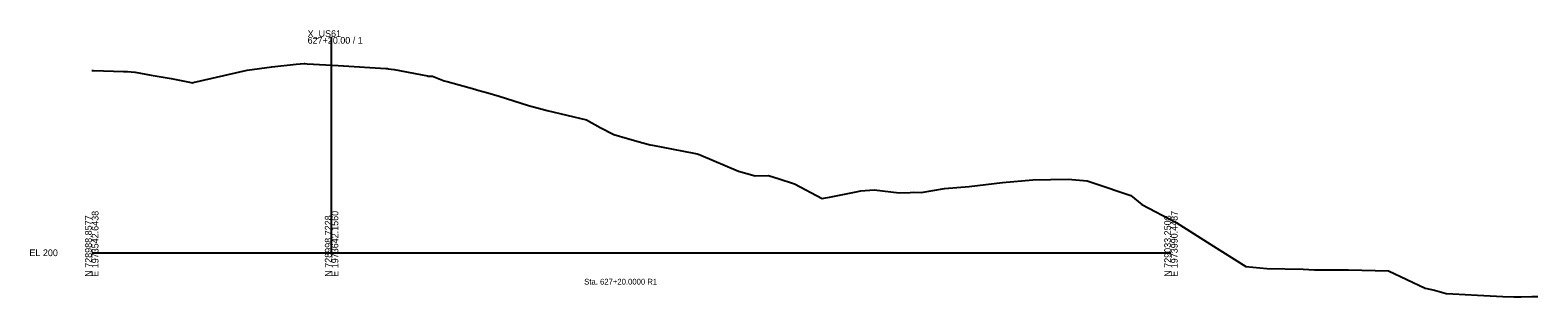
# Model space of a CAD drawing. Extents: x -26 to 630, y -39 to 9098.
# Drawn here: x -26 to 603, y 7982 to 8093 of the extents above; entities that cross this region are included whole.
import ezdxf

# ---------------------------------------------------------------- set-up
doc = ezdxf.new("R2010")
doc.units = 0
for name, color, linetype in [('Draft_XS_Grid', 7, 'Continuous'), ('Draft_XS_Text', 7, 'Continuous'), ('DTM_X_GROUND', 7, 'Continuous'), ('XS_CELL', 7, 'Continuous')]:
    doc.layers.add(name, color=color, linetype=linetype)

msp = doc.modelspace()

# ---------------------------------------------------------------- linework, layer by layer
at = {"layer": 'DTM_X_GROUND'}
msp.add_lwpolyline([(0, 8076.05), (0.74, 8076.06), (13.22, 8075.66), (14.93, 8075.6), (17.96, 8075.3), (18.04, 8075.3), (24.75, 8074.11), (33.1, 8072.62), (40.81, 8071.09), (41.84, 8070.89), (42.24, 8070.99), (64.86, 8076.14), (75.07, 8077.6), (85.2, 8078.68), (88.58, 8078.9), (88.78, 8078.91), (89.83, 8078.86), (102.75, 8078.16), (122.67, 8076.85), (123.48, 8076.79), (123.61, 8076.77), (126.15, 8076.41), (137.04, 8074.33), (139.99, 8073.75), (140.27, 8073.67), (141.64, 8073.7), (142.13, 8073.63), (146.24, 8071.98), (147, 8071.77), (148.15, 8071.44), (159.7, 8068.23), (161.01, 8067.77), (165.12, 8066.69), (169.91, 8065.31), (182.13, 8061.41), (189.92, 8059.32), (206.29, 8055.46), (212.05, 8052.3), (217.72, 8049.38), (223.35, 8047.65), (229.76, 8045.89), (232.78, 8045.06), (232.9, 8045.06), (233.76, 8044.9), (250.99, 8041.58), (252.5, 8041.29), (253.27, 8040.99), (253.98, 8040.72), (269.67, 8033.98), (276.59, 8032.07), (282.2, 8032.24), (286.62, 8030.82), (292.59, 8028.89), (293.01, 8028.76), (304.59, 8022.62), (305.95, 8022.97), (307.64, 8023.24), (318.73, 8025.48), (320.63, 8025.87), (326.21, 8026.31), (336.69, 8025.05), (341.31, 8025.2), (342.85, 8025.24), (345.85, 8025.08), (355.64, 8026.87), (365.86, 8027.63), (379.78, 8029.27), (392.38, 8030.37), (407.17, 8030.74), (415.12, 8029.96), (418.02, 8029.02), (433.23, 8023.9), (437.83, 8020.17), (452.15, 8012.59), (466.62, 8003.51), (481.21, 7994.22), (489.94, 7993.38), (505.14, 7993.18), (509.81, 7992.96), (516.36, 7992.91), (524.05, 7992.92), (540.68, 7992.49), (556.02, 7985.22), (559.94, 7984.35), (564.77, 7983), (567.5, 7982.87), (577.85, 7982.36), (588.46, 7981.71), (592.95, 7981.63), (595.24, 7981.67), (595.64, 7981.68), (596.07, 7981.68), (600.45, 7981.76), (601.31, 7981.77), (601.94, 7981.77), (602.25, 7981.78), (602.51, 7981.79), (602.72, 7981.8), (602.83, 7981.8), (602.9, 7981.81), (602.95, 7981.82), (603.01, 7981.82)], dxfattribs=at)
at = {"layer": 'XS_CELL'}
for p, q in [((100, 8000), (100, 8090)), ((0, 8000), (100, 8000)), ((100, 8000), (450, 8000))]:
    msp.add_line(p, q, dxfattribs=at)

# ---------------------------------------------------------------- texts
at = {"layer": 'Draft_XS_Grid'}
msp.add_text('-', height=0.0001, dxfattribs=at).set_placement((0, 8000))
at = {"layer": 'Draft_XS_Text'}
msp.add_text('Sta. 627+20.0000 R1', height=2.4, dxfattribs=at).set_placement((205.34, 7986.75))
at = {"layer": 'XS_CELL'}
for s, p in [('X_US61', (90, 8090)), ('627+20.00 / 1', (90, 8087.2)), ('EL 200', (-26, 7998.6))]:
    msp.add_text(s, height=2.8, dxfattribs=at).set_placement(p)
for s, p in [('E 1973542.6438', (2.8, 7990)), ('E 1973642.1560', (102.8, 7990)), ('E 1973990.4487', (452.8, 7990)), ('N 728988.8577', (0, 7990)), ('N 728998.7228', (100, 7990)), ('N 729033.2508', (450, 7990))]:
    msp.add_text(s, height=2.8, rotation=90, dxfattribs=at).set_placement(p)

doc.saveas('drawing.dxf')
